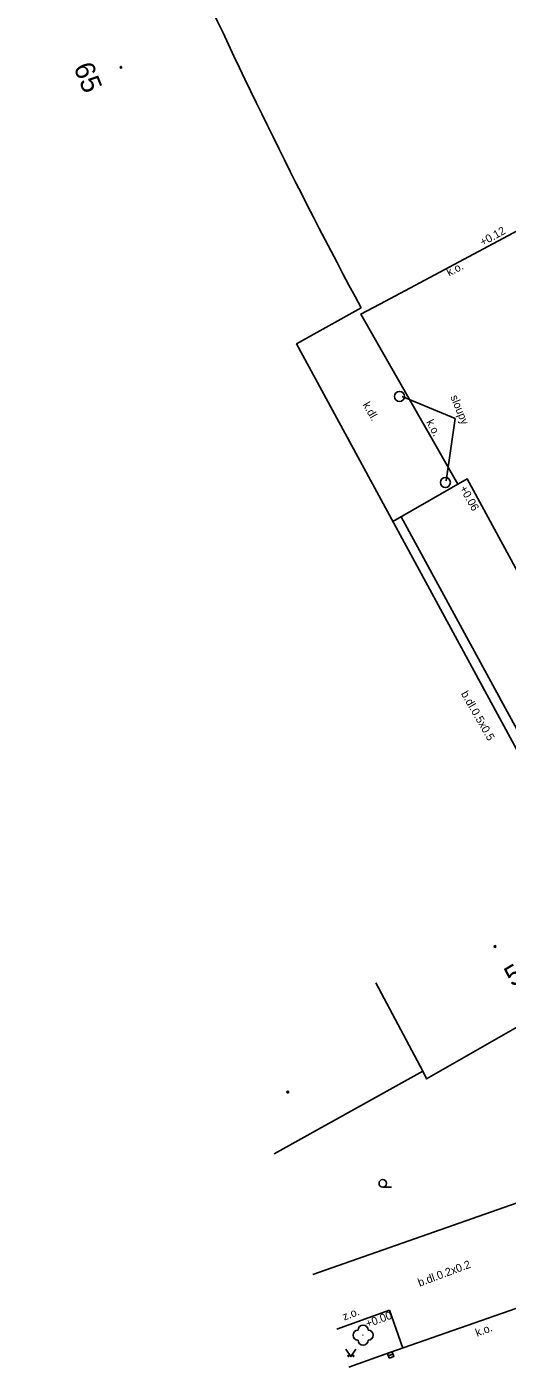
# Model space of a CAD drawing. Extents: x -598954 to -598762, y -1159533 to -1159269.
# Drawn here: x -598954.1 to -598930.1, y -1159375.5 to -1159308.5 of the extents above; entities that cross this region are included whole.
import ezdxf

# ---------------------------------------------------------------- set-up
doc = ezdxf.new("R2010")
doc.units = 0
for name, color, linetype in [('Vrstva 10', 7, 'Continuous'), ('Vrstva 14', 7, 'Continuous'), ('Vrstva 15', 7, 'Continuous'), ('Vrstva 25', 7, 'Continuous'), ('Vrstva 4', 7, 'Continuous'), ('Vrstva 43', 7, 'Continuous'), ('Vrstva 49', 7, 'Continuous'), ('Vrstva 50', 7, 'Continuous'), ('Vrstva 7', 7, 'Continuous')]:
    doc.layers.add(name, color=color, linetype=linetype)

msp = doc.modelspace()

# ---------------------------------------------------------------- linework, layer by layer
at = {"layer": 'Vrstva 10'}
msp.add_lwpolyline([(-598939.825, -1159370.844), (-598925.788, -1159365.919)], dxfattribs=at)
at = {"layer": 'Vrstva 14'}
msp.add_line((-598936.325, -1159366.47), (-598935.888, -1159366.47), dxfattribs=at)
msp.add_lwpolyline([(-598938.167, -1159374.563), (-598937.917, -1159374.938), (-598937.667, -1159374.563)], dxfattribs=at)
for centre, radius in [((-598936.325, -1159366.283), 0.188), ((-598937.309, -1159373.871), 0.00025), ((-598938.042, -1159374.913), 0.025), ((-598937.792, -1159374.913), 0.025)]:
    msp.add_circle(centre, radius, dxfattribs=at)
for centre, start, end in [((-598937.559, -1159373.871), 89.99999, 269.99999), ((-598937.309, -1159373.621), 0, 179.99999), ((-598937.059, -1159373.871), 270, 89.99999), ((-598937.309, -1159374.121), 179.99999, 359.99999)]:
    msp.add_arc(centre, 0.25, start, end, dxfattribs=at)
at = {"layer": 'Vrstva 15'}
for centre in [(-598949.423, -1159310.492), (-598930.709, -1159354.441), (-598941.078, -1159361.719)]:
    msp.add_circle(centre, 0.0438, dxfattribs=at)
at = {"layer": 'Vrstva 25'}
msp.add_line((-598936.052, -1159374.905), (-598935.817, -1159374.82), dxfattribs=at)
msp.add_lwpolyline([(-598936.01, -1159375.023), (-598935.774, -1159374.938), (-598935.859, -1159374.702), (-598936.095, -1159374.787)], close=True, dxfattribs=at)
at = {"layer": 'Vrstva 4'}
msp.add_line((-598934.32, -1159360.67), (-598936.671, -1159356.257), dxfattribs=at)
for points in [[(-598929.315, -1159345.154), (-598940.64, -1159324.32), (-598937.41, -1159322.52)], [(-598941.763, -1159364.806), (-598934.32, -1159360.67), (-598934.13, -1159361.06), (-598923.86, -1159355.19), (-598929.315, -1159345.154)]]:
    msp.add_lwpolyline(points, dxfattribs=at)
for centre in [(-598935.488, -1159326.944), (-598933.191, -1159331.247)]:
    msp.add_circle(centre, 0.25, dxfattribs=at)
msp.add_arc((-598687.823, -1159188.483), 283.302, 199.94025, 208.23736, dxfattribs=at)
at = {"layer": 'Vrstva 49'}
for p in [(-598935.356, -1159326.952), (-598933.157, -1159331.165)]:
    msp.add_line(p, (-598932.704, -1159328.045), dxfattribs=at)
at = {"layer": 'Vrstva 7'}
for p in [(-598938.631, -1159373.566), (-598935.328, -1159374.514)]:
    msp.add_line(p, (-598935.988, -1159372.626), dxfattribs=at)
for points in [[(-598923.928, -1159315.538), (-598929.815, -1159318.78), (-598936.193, -1159322.175), (-598937.423, -1159322.827), (-598932.562, -1159331.334)], [(-598926.524, -1159341.304), (-598932.1, -1159331.07), (-598935.816, -1159333.194)], [(-598935.404, -1159332.959), (-598930.002, -1159342.88), (-598923.186, -1159355.312)], [(-598938.024, -1159375.472), (-598935.971, -1159374.739), (-598924.031, -1159370.565), (-598919.831, -1159369.081), (-598918.727, -1159368.693), (-598916.665, -1159371.52)]]:
    msp.add_lwpolyline(points, dxfattribs=at)

# ---------------------------------------------------------------- texts
at = {"layer": 'Vrstva 43'}
for s, rotation, p in [('65', 291.83846, (-598951.812, -1159310.48)), ('5', 30.79188, (-598929.852, -1159356.484))]:
    msp.add_text(s, height=1, rotation=rotation, dxfattribs=at).set_placement(p)
at = {"layer": 'Vrstva 49'}
for s, rotation, p in [('k.o.', 27.25798, (-598933.007, -1159320.95)), ('k.dl.', 299.89772, (-598937.346, -1159327.357)), ('sloupy', 292.28631, (-598932.949, -1159326.963)), ('k.o.', 298.05502, (-598934.163, -1159328.224)), ('b.dl.0.5x0.5', 299.89772, (-598932.425, -1159341.801)), ('b.dl.0.2x0.2', 20.37385, (-598934.482, -1159371.449)), ('z.o.', 21.05976, (-598938.253, -1159373.147)), ('k.o.', 20.30966, (-598931.603, -1159373.952))]:
    msp.add_text(s, height=0.4, rotation=rotation, dxfattribs=at).set_placement(p)
at = {"layer": 'Vrstva 50'}
for s, rotation, p in [('+0.12', 29.06616, (-598931.325, -1159319.438)), ('+0.06', 299.62466, (-598932.496, -1159331.537)), ('+0.00', 20.30966, (-598937.095, -1159373.504))]:
    msp.add_text(s, height=0.4, rotation=rotation, dxfattribs=at).set_placement(p)

doc.saveas('drawing.dxf')
